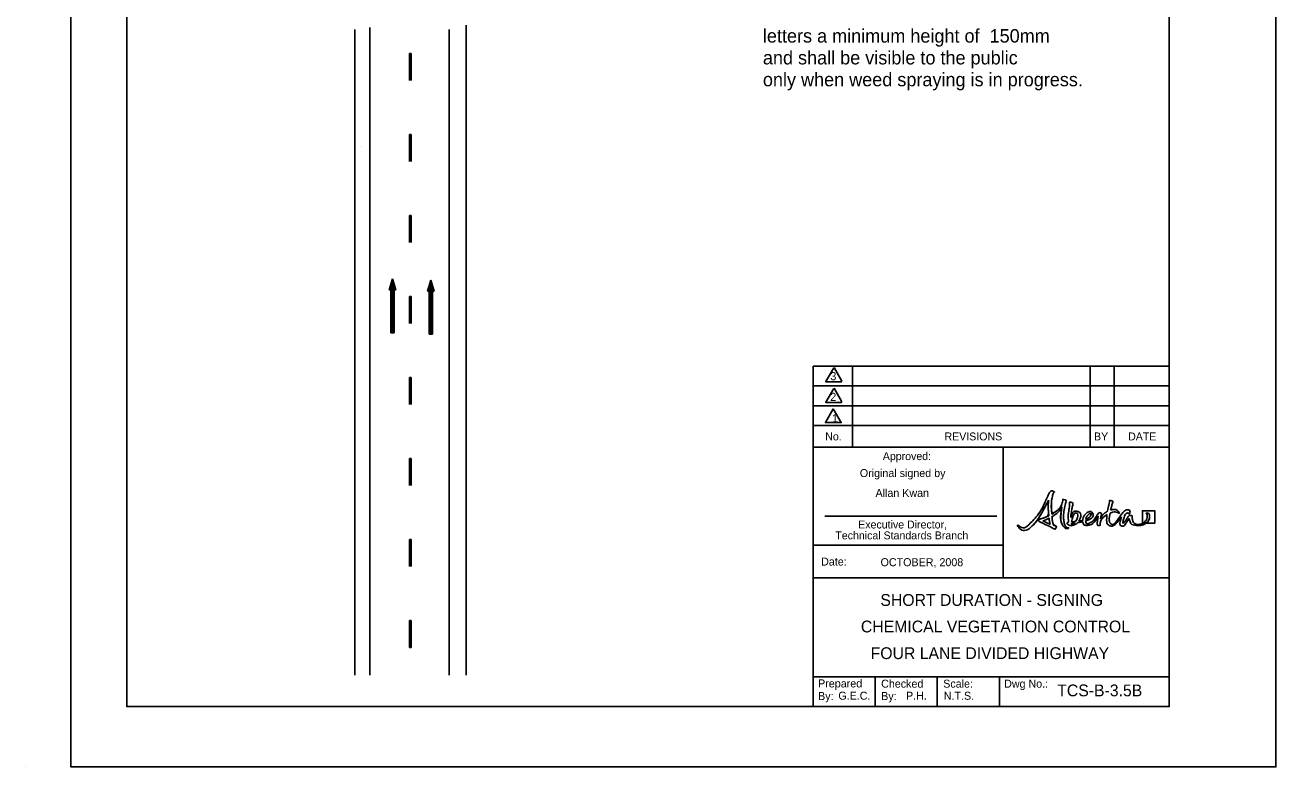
# Model space of a CAD drawing. Extents: x 1570 to 1794, y 169 to 448.
# Drawn here: x 1570.2 to 1794.5, y 169 to 301.9 of the extents above; entities that cross this region are included whole.
import ezdxf

# ---------------------------------------------------------------- set-up
doc = ezdxf.new("R2010")
doc.units = 0
for name, color, linetype in [('Level 10', 7, 'Continuous'), ('Level 2', 7, 'Continuous'), ('Level 53', 7, 'Continuous'), ('Level 60', 7, 'Continuous')]:
    doc.layers.add(name, color=color, linetype=linetype)

msp = doc.modelspace()

# ---------------------------------------------------------------- linework, layer by layer
at = {"layer": 'Level 10'}
for p, q in [((1629.33, 301.16), (1629.33, 185.45)), ((1632.06, 301.53), (1632.06, 185.45)), ((1646.28, 301.16), (1646.28, 185.45)), ((1649.3, 301.9), (1649.3, 185.45)), ((1630.42, 280.2), (1630.42, 280.2)), ((1636.12, 256.46), (1635.54, 254.53)), ((1635.9, 255.74), (1635.9, 246.79)), ((1635.97, 255.98), (1635.97, 246.79)), ((1636.05, 256.22), (1636.05, 246.79)), ((1636.12, 256.46), (1636.12, 246.79)), ((1636.12, 256.46), (1636.7, 254.53)), ((1636.19, 256.22), (1636.19, 246.79)), ((1636.26, 255.98), (1636.26, 246.79)), ((1636.34, 255.74), (1636.34, 246.79)), ((1642.99, 256.21), (1642.41, 254.28)), ((1642.84, 255.73), (1642.84, 246.54)), ((1642.91, 255.97), (1642.91, 246.54)), ((1642.99, 256.21), (1642.99, 246.54)), ((1642.99, 256.21), (1643.57, 254.28)), ((1643.06, 255.97), (1643.06, 246.54)), ((1643.13, 255.73), (1643.13, 246.54)), ((1635.54, 254.53), (1635.83, 254.53)), ((1635.61, 254.77), (1635.61, 254.53)), ((1635.68, 255.01), (1635.68, 254.53)), ((1635.75, 255.25), (1635.75, 254.53)), ((1635.83, 255.5), (1635.83, 246.79)), ((1635.83, 254.53), (1635.83, 246.79)), ((1636.41, 255.5), (1636.41, 246.79)), ((1636.41, 254.53), (1636.41, 246.79)), ((1636.41, 254.53), (1636.7, 254.53)), ((1636.48, 255.25), (1636.48, 254.53)), ((1636.55, 255.01), (1636.55, 254.53)), ((1636.63, 254.77), (1636.63, 254.53)), ((1642.41, 254.28), (1642.7, 254.28)), ((1642.48, 254.52), (1642.48, 254.28)), ((1642.55, 254.76), (1642.55, 254.28)), ((1642.62, 255), (1642.62, 254.28)), ((1642.7, 255.25), (1642.7, 246.54)), ((1642.7, 254.28), (1642.7, 246.54)), ((1642.77, 255.49), (1642.77, 246.54)), ((1643.2, 255.49), (1643.2, 246.54)), ((1643.28, 255.25), (1643.28, 246.54)), ((1643.28, 254.28), (1643.28, 246.54)), ((1643.28, 254.28), (1643.57, 254.28)), ((1643.35, 255), (1643.35, 254.28)), ((1643.42, 254.76), (1643.42, 254.28)), ((1643.49, 254.52), (1643.49, 254.28)), ((1635.83, 246.79), (1636.41, 246.79)), ((1642.7, 246.54), (1643.28, 246.54)), ((1570.24, 169.02), (1570.24, 169.02))]:
    msp.add_line(p, q, dxfattribs=at)
at = {"layer": 'Level 2'}
for p, q in [((1639.15, 296.86), (1639.15, 292.02)), ((1639.44, 296.86), (1639.15, 296.86)), ((1639.44, 292.02), (1639.44, 296.86)), ((1639.15, 282.35), (1639.15, 277.51)), ((1639.44, 282.35), (1639.15, 282.35)), ((1639.44, 277.51), (1639.44, 282.35)), ((1639.15, 267.83), (1639.15, 262.99)), ((1639.44, 267.83), (1639.15, 267.83)), ((1639.44, 262.99), (1639.44, 267.83)), ((1639.15, 253.32), (1639.15, 248.48)), ((1639.44, 253.32), (1639.15, 253.32)), ((1639.44, 248.48), (1639.44, 253.32)), ((1639.15, 238.8), (1639.15, 233.97)), ((1639.44, 238.8), (1639.15, 238.8)), ((1639.44, 233.97), (1639.44, 238.8)), ((1639.15, 224.29), (1639.15, 219.45)), ((1639.44, 224.29), (1639.15, 224.29)), ((1639.44, 219.45), (1639.44, 224.29)), ((1639.15, 209.78), (1639.15, 204.94)), ((1639.44, 209.78), (1639.15, 209.78)), ((1639.44, 204.94), (1639.44, 209.78)), ((1639.15, 195.26), (1639.15, 190.42)), ((1639.44, 195.26), (1639.15, 195.26)), ((1639.44, 190.42), (1639.44, 195.26)), ((1639.15, 190.42), (1639.44, 190.42))]:
    msp.add_line(p, q, dxfattribs=at)
at = {"layer": 'Level 53'}
msp.add_line((1771.14, 212.69), (1770.59, 212.69), dxfattribs=at)
msp.add_lwpolyline([(1771.14, 212.69), (1772.75, 212.69), (1772.75, 214.92), (1770.52, 214.92), (1770.52, 212.69), (1770.59, 212.69)], dxfattribs=at)
for points, degree in [([(1757.15, 211.88), (1756.91, 211.92), (1756.6, 212.24), (1756.5, 212.78), (1756.33, 213.75), (1756.43, 214.7), (1756.72, 216.12), (1756.77, 216.39), (1756.96, 216.86), (1756.37, 216.95), (1756.19, 216.98), (1756.28, 216.88), (1756.23, 216.64), (1756.01, 215.58), (1755.14, 214.82), (1754.27, 214.31), (1754.18, 215.52), (1754.22, 216.86), (1754.45, 217.69), (1754.64, 218.39), (1754.87, 218.26), (1754.58, 218.4), (1754.29, 218.56), (1753.96, 218.35), (1753.7, 217.84), (1753.44, 217.32), (1752.25, 214.5), (1750.34, 212.6), (1749.36, 211.63), (1748.47, 212.13), (1748.3, 212.28), (1748.15, 212.4), (1748.1, 212.21), (1748.28, 212.02), (1749.07, 211.17), (1750.22, 211.66), (1750.65, 212.08), (1751.81, 213.24), (1753.16, 215.74), (1753.71, 216.8), (1753.66, 216.21), (1753.64, 215.2), (1753.75, 214.03), (1753.16, 213.74), (1752.63, 213.57), (1752.38, 213.5), (1752.11, 213.43), (1751.94, 213.32), (1751.93, 213.2), (1751.93, 213.06), (1752.11, 212.94), (1752.37, 212.82), (1752.84, 212.6), (1754.21, 211.95), (1754.55, 211.75), (1754.84, 211.58), (1754.98, 211.71), (1755.07, 211.9), (1755.18, 212.13), (1754.87, 212.27), (1754.58, 212.36), (1754.46, 212.76), (1754.37, 213.29), (1754.31, 213.88), (1755.01, 214.31), (1755.69, 214.88), (1756.09, 215.6), (1755.99, 215), (1755.73, 212.97), (1756.38, 212.11), (1756.52, 211.92), (1756.83, 211.71), (1757.13, 211.74), (1757.28, 211.76), (1757.35, 211.85), (1757.33, 211.88), (1757.32, 211.91), (1757.24, 211.87), (1757.15, 211.88)], 3), ([(1754.27, 214.31), (1754.18, 215.52), (1754.22, 216.86), (1754.45, 217.69), (1754.64, 218.39), (1754.87, 218.26), (1754.58, 218.4), (1754.29, 218.56), (1753.96, 218.35), (1753.7, 217.84), (1753.44, 217.32), (1752.25, 214.5), (1750.34, 212.6), (1749.36, 211.63), (1748.47, 212.13), (1748.3, 212.28), (1748.15, 212.4), (1748.1, 212.21), (1748.28, 212.02), (1749.07, 211.17), (1750.22, 211.66), (1750.65, 212.08), (1751.81, 213.24), (1753.16, 215.74), (1753.71, 216.8)], 3), ([(1753.71, 216.8), (1753.66, 216.21), (1753.64, 215.2), (1753.75, 214.03)], 2), ([(1757.15, 211.88), (1756.91, 211.92), (1756.6, 212.24), (1756.5, 212.78), (1756.33, 213.75), (1756.43, 214.7), (1756.72, 216.12), (1756.77, 216.39), (1756.96, 216.86), (1756.37, 216.95), (1756.19, 216.98), (1756.28, 216.88), (1756.23, 216.64), (1756.01, 215.58), (1755.14, 214.82), (1754.27, 214.31)], 3), ([(1754.31, 213.88), (1755.01, 214.31), (1755.69, 214.88), (1756.09, 215.6)], 2), ([(1756.09, 215.6), (1755.99, 215), (1755.73, 212.97), (1756.38, 212.11), (1756.52, 211.92), (1756.83, 211.71), (1757.13, 211.74), (1757.28, 211.76), (1757.35, 211.85), (1757.33, 211.88), (1757.32, 211.91), (1757.24, 211.87), (1757.15, 211.88)], 3), ([(1757.69, 213.72), (1757.74, 214.29), (1757.83, 214.99), (1757.96, 215.63), (1758.01, 215.9), (1758.19, 216.36), (1757.61, 216.45), (1757.42, 216.48), (1757.45, 216.4), (1757.47, 216.14), (1757.49, 215.81), (1757.12, 213.77), (1757.31, 212.87)], 3), ([(1764.84, 215.07), (1764.91, 215.36), (1764.98, 215.67), (1765.07, 215.96), (1765.14, 216.23), (1765.36, 216.69), (1764.79, 216.78), (1764.6, 216.81), (1764.68, 216.72), (1764.62, 216.47), (1764.51, 216.02), (1764.37, 215.42), (1764.27, 214.83)], 3), ([(1753.75, 214.03), (1753.16, 213.74), (1752.63, 213.57), (1752.38, 213.5), (1752.11, 213.43), (1751.94, 213.32), (1751.93, 213.2), (1751.93, 213.06), (1752.11, 212.94), (1752.37, 212.82), (1752.84, 212.6), (1754.21, 211.95), (1754.55, 211.75), (1754.84, 211.58), (1754.98, 211.71), (1755.07, 211.9), (1755.18, 212.13), (1754.87, 212.27), (1754.58, 212.36)], 3), ([(1752.68, 213.09), (1752.99, 213.21), (1753.38, 213.37), (1753.8, 213.59)], 2), ([(1752.68, 213.09), (1752.99, 213.21), (1753.38, 213.37), (1753.8, 213.59), (1753.85, 213.12), (1753.91, 212.77), (1753.98, 212.52), (1753.68, 212.63), (1753.25, 212.81), (1752.68, 213.09)], 3), ([(1753.98, 212.52), (1753.68, 212.63), (1753.25, 212.81), (1752.68, 213.09)], 2), ([(1753.8, 213.59), (1753.85, 213.12), (1753.91, 212.77), (1753.98, 212.52)], 2), ([(1754.58, 212.36), (1754.46, 212.76), (1754.37, 213.29), (1754.31, 213.88)], 2), ([(1759.13, 213.06), (1759.54, 213.74), (1759.51, 214.65), (1758.9, 214.8), (1758.2, 214.98), (1757.84, 214.29), (1757.69, 213.72)], 3), ([(1757.84, 212.93), (1757.94, 213.65), (1758.31, 214.64), (1758.77, 214.48), (1759.04, 214.39), (1758.9, 213.55), (1758.56, 213)], 3), ([(1759.83, 213.18), (1759.62, 213.14), (1759.39, 213.1), (1759.13, 213.06)], 2), ([(1760.35, 213.09), (1760.45, 213.12), (1760.54, 213.15), (1760.61, 213.18), (1761.49, 213.57), (1761.8, 214.16), (1761.57, 214.52), (1761.36, 214.86), (1760.75, 214.76), (1760.27, 214.25), (1760.03, 214), (1759.85, 213.57), (1759.83, 213.18)], 3), ([(1759.83, 212.96), (1759.88, 212.57), (1760.14, 212.27), (1760.73, 212.32), (1761.58, 212.4), (1762.33, 213.44), (1762.62, 213.94)], 3), ([(1763.03, 213.5), (1763.08, 213.78), (1763.17, 214.08), (1763.18, 214.29), (1763.18, 214.51), (1763.03, 214.56), (1762.98, 214.57), (1762.85, 214.61), (1762.7, 214.54), (1762.55, 214.33), (1762.19, 213.83), (1761.75, 213.05), (1761.07, 212.72), (1760.58, 212.48), (1760.37, 212.72), (1760.35, 213.09)], 3), ([(1760.83, 214.21), (1761.12, 214.48), (1761.27, 214.46), (1761.31, 214.39), (1761.39, 214.23), (1761.04, 213.66), (1760.38, 213.36)], 3), ([(1760.38, 213.36), (1760.43, 213.66), (1760.59, 213.99), (1760.83, 214.21)], 2), ([(1762.62, 213.94), (1762.57, 213.4), (1762.22, 212.23), (1762.81, 212.29), (1763.04, 212.32), (1762.94, 212.35), (1762.96, 212.55), (1763.01, 213.26), (1763.6, 213.86), (1764.18, 214.23)], 3), ([(1764.27, 214.83), (1763.79, 214.56), (1763.35, 214.1), (1763.03, 213.5)], 2), ([(1764.18, 214.23), (1764.08, 213.36), (1764.11, 212.59), (1764.51, 212.34), (1765.23, 211.89), (1766.25, 213.08), (1766.81, 213.81)], 3), ([(1769.9, 212.49), (1768.98, 212.49), (1768.75, 213.21), (1768.7, 213.56), (1768.67, 213.79), (1768.72, 214.13), (1768.32, 214.09), (1768.04, 214.05), (1767.78, 213.5), (1767.42, 213.04), (1767.11, 212.64), (1766.98, 212.68), (1767.05, 213.02), (1767.14, 213.45), (1767.49, 214.45), (1767.9, 214.53), (1768.09, 214.56), (1768.16, 214.23), (1768.25, 214.44), (1768.34, 214.65), (1768.25, 215.09), (1767.83, 215.09), (1767.54, 215.09), (1767.18, 214.78), (1766.89, 214.42), (1766.63, 214.11), (1765.35, 212.22), (1764.81, 212.63), (1764.56, 212.82), (1764.58, 213.6), (1764.74, 214.51)], 3), ([(1764.74, 214.51), (1765.38, 214.76), (1765.91, 214.68), (1766.21, 214.53), (1766.36, 214.46), (1766.38, 214.47), (1766.31, 214.64), (1766.22, 214.88), (1765.71, 215.25), (1764.9, 215.08), (1764.88, 215.07), (1764.86, 215.07), (1764.84, 215.07)], 3), ([(1766.81, 213.81), (1766.53, 213.16), (1766.36, 212.34), (1766.8, 212.21), (1767.3, 212.06), (1767.7, 212.9), (1768.16, 213.54)], 3), ([(1768.16, 213.54), (1768.22, 213.08), (1768.52, 212.29), (1769.76, 212.29), (1770.32, 212.29), (1770.79, 212.44), (1771.14, 212.69)], 3), ([(1770.52, 214.92), (1770.52, 214.92), (1770.52, 212.69), (1770.52, 212.69), (1770.52, 212.69), (1770.59, 212.69), (1770.59, 212.69), (1771.07, 212.98), (1771.4, 213.54), (1771.4, 213.99), (1771.4, 214.39), (1771.19, 214.37), (1771.21, 214.42), (1771.28, 214.58), (1771.77, 214.49), (1771.8, 213.93), (1771.83, 213.46), (1771.58, 213), (1771.14, 212.69), (1771.14, 212.69), (1772.75, 212.69), (1772.75, 212.69), (1772.75, 212.69), (1772.75, 214.92), (1772.75, 214.92), (1772.75, 214.92), (1770.52, 214.92), (1770.52, 214.92)], 3), ([(1770.59, 212.69), (1771.07, 212.98), (1771.4, 213.54), (1771.4, 213.99), (1771.4, 214.39), (1771.19, 214.37), (1771.21, 214.42), (1771.28, 214.58), (1771.77, 214.49), (1771.8, 213.93), (1771.83, 213.46), (1771.58, 213), (1771.14, 212.69)], 3), ([(1757.31, 212.87), (1757.06, 212.79), (1756.96, 212.6), (1757.28, 212.4), (1757.5, 212.27), (1757.99, 212.22), (1758.49, 212.46), (1758.67, 212.55), (1758.82, 212.67), (1758.95, 212.82)], 3), ([(1757.77, 212.5), (1757.8, 212.53), (1757.82, 212.57), (1757.82, 212.62), (1757.82, 212.65), (1757.82, 212.68), (1757.82, 212.71)], 3), ([(1757.97, 212.5), (1757.89, 212.49), (1757.82, 212.49), (1757.77, 212.5)], 2), ([(1757.82, 212.71), (1757.95, 212.72), (1758.14, 212.73), (1758.38, 212.75)], 2), ([(1758.56, 213), (1758.33, 212.97), (1758.09, 212.95), (1757.84, 212.93)], 2), ([(1758.38, 212.75), (1758.25, 212.62), (1758.12, 212.53), (1757.97, 212.5)], 2), ([(1758.95, 212.82), (1759.24, 212.86), (1759.55, 212.9), (1759.83, 212.96)], 2), ([(1770.59, 212.69), (1770.38, 212.57), (1770.15, 212.49), (1769.9, 212.49)], 2)]:
    msp.add_open_spline(points, degree=degree, dxfattribs=at)
at = {"layer": 'Level 60'}
for p, q in [((1711.5, 234.37), (1711.5, 240.84)), ((1775.38, 240.84), (1711.5, 240.84)), ((1718.59, 234.37), (1718.59, 240.84)), ((1761.18, 240.84), (1761.18, 226.29)), ((1765.49, 240.84), (1765.49, 226.29)), ((1775.38, 237.29), (1711.5, 237.29)), ((1711.5, 226.29), (1711.5, 234.37)), ((1775.38, 233.75), (1711.5, 233.75)), ((1718.59, 226.29), (1718.59, 234.37)), ((1775.38, 230.2), (1711.5, 230.2)), ((1745.72, 228.68), (1745.72, 228.68)), ((1711.5, 179.83), (1711.5, 226.29)), ((1711.5, 226.29), (1775.38, 226.29)), ((1745.55, 226.29), (1745.55, 202.88)), ((1745.57, 226.29), (1745.57, 226.29)), ((1713.61, 213.98), (1744.41, 213.98)), ((1711.5, 208.74), (1745.55, 208.74)), ((1711.5, 202.88), (1775.35, 202.88)), ((1711.5, 185.15), (1775.35, 185.15)), ((1722.63, 179.83), (1722.63, 185.15)), ((1733.76, 179.83), (1733.76, 185.15)), ((1744.89, 185.15), (1744.89, 179.83)), ((1588.47, 179.83), (1588.47, 179.83)), ((1726.97, 179.83), (1726.97, 179.83)), ((1775.35, 179.83), (1775.35, 179.83)), ((1775.35, 179.83), (1775.35, 179.83)), ((1578.47, 169.02), (1578.47, 169.02))]:
    msp.add_line(p, q, dxfattribs=at)
for points in [[(1794.47, 448.02), (1578.47, 448.02), (1578.47, 169.02), (1794.47, 169.02)], [(1775.35, 437.21), (1588.47, 437.21), (1588.47, 179.83), (1775.35, 179.83)], [(1715.12, 233.18), (1713.7, 230.71), (1716.54, 230.71)]]:
    msp.add_lwpolyline(points, close=True, dxfattribs=at)
for points in [[(1715.2, 240.51), (1713.81, 238.09)], [(1716.68, 238.16), (1715.29, 240.59)], [(1713.81, 238.09), (1713.78, 238.04), (1716.62, 238.04), (1716.6, 238.09)], [(1715.2, 236.8), (1713.81, 234.37)], [(1716.68, 234.45), (1715.29, 236.87)], [(1713.81, 234.37), (1713.78, 234.33), (1716.62, 234.33), (1716.6, 234.37)]]:
    msp.add_lwpolyline(points, dxfattribs=at)

# ---------------------------------------------------------------- texts
at = {"layer": 'Level 10'}
for s, p in [('  letters a minimum height of  150mm', (1700.71, 298.8)), ('  and shall be visible to the public', (1700.71, 294.89)), ('  only when weed spraying is in progress.', (1700.71, 290.97))]:
    msp.add_text(s, height=2.419, dxfattribs=at).set_placement(p)
at = {"layer": 'Level 60'}
for s, height, p in [('3', 1.45, (1714.59, 238.31)), ('2', 1.45, (1714.58, 234.6)), ('1', 1.45, (1714.9, 230.77)), ('No.', 1.419, (1713.68, 227.53)), ('REVISIONS', 1.419, (1735.06, 227.53)), ('BY', 1.419, (1761.86, 227.53)), ('DATE', 1.419, (1767.97, 227.53)), ('Date:', 1.433, (1712.94, 205.1)), ('SHORT DURATION - SIGNING', 2.115, (1723.56, 197.88)), ('CHEMICAL VEGETATION CONTROL', 2.115, (1720.07, 193.13)), ('Prepared', 1.44, (1712.39, 183.27)), ('Checked', 1.433, (1723.7, 183.23)), ('Scale:', 1.433, (1734.83, 183.23)), ('Dwg No.:', 1.433, (1745.75, 183.23)), ('By:', 1.44, (1712.39, 181.01)), ('G.E.C.', 1.433, (1716.03, 181.07)), ('By:', 1.44, (1723.7, 181.01)), ('P.H.', 1.433, (1728.16, 181.07)), ('    N.T.S.   ', 1.4329, (1732.8, 181.06))]:
    msp.add_text(s, height=height, rotation=360, dxfattribs=at).set_placement(p)
for s, height, p in [('Approved:', 1.419, (1724, 224)), ('Original signed by', 1.434, (1719.88, 220.96)), ('Allan Kwan', 1.434, (1722.69, 217.4)), ('Executive Director,', 1.4187, (1719.59, 211.75)), ('Technical Standards Branch', 1.4187, (1715.49, 209.8)), ('OCTOBER, 2008', 1.434, (1723.6, 204.99)), ('FOUR LANE DIVIDED HIGHWAY', 2.1152, (1721.82, 188.35)), ('TCS-B-3.5B', 2.115, (1755.26, 181.68))]:
    msp.add_text(s, height=height, dxfattribs=at).set_placement(p)

doc.saveas('drawing.dxf')
